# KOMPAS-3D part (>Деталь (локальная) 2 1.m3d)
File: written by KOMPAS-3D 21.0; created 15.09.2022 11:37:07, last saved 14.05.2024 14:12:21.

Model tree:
1. Эскиз:1

Referenced files in C:\Program Files\Ascon\Libs\EasySteel\: Rolled metal.kle, StandartSolutions.kle, DSTVProperties.lpt
Referenced files in W:\Шаблоны чертежей\: Констр. чертеж А3 гориз. перв. лист.cdt
Referenced files in C:\Program Files\Ascon\Libs\EasySteel\BeltEndings\: 
Referenced files in C:\Program Files\Ascon\Libs\EasySteel\Punctures\: 
Referenced files in C:\Program Files\Ascon\Libs\EasySteel\Insulations\: 
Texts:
  Уголок равнополочный по ГОСТ 8509-93 (Спец)
  config2DpacketName
  config2DstdSizeID
  Констр. чертеж А3 гориз. перв. лист.cdt
  Болт ГОСТ 22353-77
  Шайба ГОСТ 22355-77
  Гайка ГОСТ 22354-77
  Нормальная пружинная шайба ГОСТ 6402-70 (исп. 1)
  SeaRox SL 436
  Сталь 09Г2С ГОСТ 19281-2014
